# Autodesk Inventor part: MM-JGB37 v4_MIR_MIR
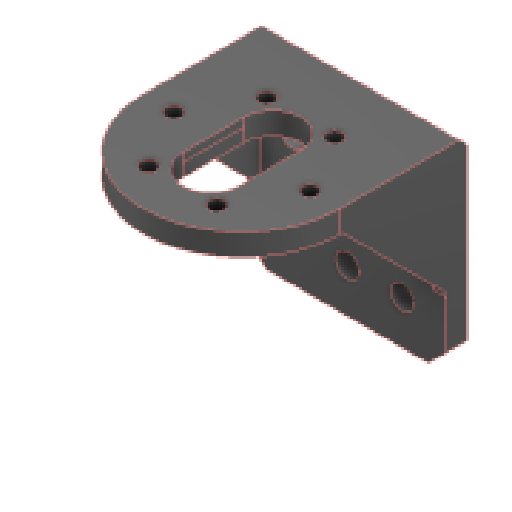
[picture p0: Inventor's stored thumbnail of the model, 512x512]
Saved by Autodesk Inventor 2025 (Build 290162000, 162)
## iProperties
Created: 2024-01
Part Number: MM-JGB37 v4_MIR_MIR
Material: Plastica PET
Document SubType Name: Modeling
Designer: R5800u
Density: 1.541 g/cm^3
Appearance: Rosso
Title: MM-JGB37 v4.step
Sending System: Autodesk Translation Framework v12.14.0.127
Preprocessor: ST-DEVELOPER v20
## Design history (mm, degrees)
derived "MM-JGB37 v4_MIR.ipt"
  sketch "Schizzo1"
    geometry: L1 (0, -42.5)-(0, 0) reference; L2 (40, -42.5)-(0, -42.5) reference; L3 (40, -42.5)-(40, 0) reference; L4 (0, 0)-(40, 0) reference; 1 further point
  sketch "Schizzo6"
    geometry: L1 (-2.5, -5)-(-2.5, 24) reference; L2 (42.5, 24)-(42.5, -5) reference; L3 (-2.5, -5)-(42.5, -5) reference; L4 (42.5, -5)-(42.5, 0) reference; L5 (42.5, 0)-(-2.5, 0) reference; L6 (-2.5, 0)-(-2.5, -5) reference; L7 (0, 0)-(40, 0) reference; L8 (0, -5)-(0, 0) reference; L9 (40, -5)-(0, -5) reference; L10 (40, -5)-(40, 0) reference; 1 further point
  sketch "Schizzo7"
    geometry: L1 (5, -5)-(29, -5) reference; L2 (29, 0)-(29, -5) reference; L3 (0, 0)-(29, 0) reference; L4 (0, 0)-(0, -44.5) reference; L5 (5, -44.5)-(0, -44.5) reference; L6 (5, -44.5)-(5, -5) reference; L7 (27.973, -5.631)-(5, -28.604) reference; A1 r 1.151 centre (29, -6.151) between (29, -5) and (27.973, -5.631) reference; 1 further point
  sketch "Schizzo8"
    geometry: L1 (10, -180.5)-(10, 19.5) reference; L2 (0, 29.5)-(300, 29.5) reference; L3 (45, 0)-(0, 0) reference; L4 (45, 0)-(45, 15.067) reference; L5 (0, 16.481)-(0, 38.869) reference; L6 (0, 0)-(0, 15.067) reference; 8 further points
  node "Piano di lavoro1"
feature "Solido1::MM-JGB37 v4_MIR.ipt" dims "d0" = 10
tag "Lavorazione contrassegno1"
sketch "Schizzo3"
  geometry: L1 (20, 0)-(20, 29) reference; L2 (-20, 29)-(20, 29) reference; L3 (-20, 29)-(-20, 0) reference; L4 (-6.5, -7)-(-6.5, 7) reference; L5 (6.5, 7)-(6.5, -7) reference; C1 r 1.75 at (15.5, 0) reference; C2 r 1.75 at (-7.75, -13.423) reference; C3 r 1.75 at (7.75, -13.423) reference; C4 r 1.75 at (7.75, 13.423) reference; C5 r 1.75 at (-15.5, 0) reference; C6 r 1.75 at (-7.75, 13.423) reference; A1 r 20 centre (0, 0) between (-20, 0) and (20, 0) reference; A2 r 6.5 centre (0, 7) between (6.5, 7) and (-6.5, 7) reference; A3 r 6.5 centre (0, -7) between (-6.5, -7) and (6.5, -7) reference; 1 further point
sketch "Schizzo5"
  geometry: L1 (20, 0)-(20, 29) reference; L2 (20, 29)-(-20, 29) reference; L3 (-20, 29)-(-20, 0) reference; L4 (6.5, 7)-(6.5, -7) reference; L5 (-6.5, -7)-(-6.5, 7) reference; L6 (-22.5, 0)-(-22.5, 31.5) reference; L7 (-22.5, 31.5)-(22.5, 31.5) reference; L8 (22.5, 31.5)-(22.5, 0) reference; L9 (22.5, 29)-(20, 29) reference; L10 (-22.5, 29)-(-20, 29) reference; C1 r 1.75 at (-7.75, 13.423) reference; C2 r 1.75 at (-15.5, 0) reference; C3 r 1.75 at (7.75, 13.423) reference; C4 r 1.75 at (7.75, -13.423) reference; C5 r 1.75 at (-7.75, -13.423) reference; C6 r 1.75 at (15.5, 0) reference; A1 r 20 centre (0, 0) between (-20, 0) and (20, 0) reference; A2 r 6.5 centre (0, -7) between (-6.5, -7) and (6.5, -7) reference; A3 r 6.5 centre (0, 7) between (6.5, 7) and (-6.5, 7) reference; A4 r 22.5 centre (0, 0) between (-22.5, 0) and (22.5, 0) reference; 1 further point
node "Solido1"
